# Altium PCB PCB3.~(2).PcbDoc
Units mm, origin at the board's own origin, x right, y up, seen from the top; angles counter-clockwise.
Board outline 50 x 50 mm, 4 copper layers (Top Layer, Internal Plane 1, Internal Plane 2, Bottom Layer), stack 0.462 mm thick; 11 components, 11 nets, 36 pads, 0 vias.
Unrouted connection lines stored in the file: 21.
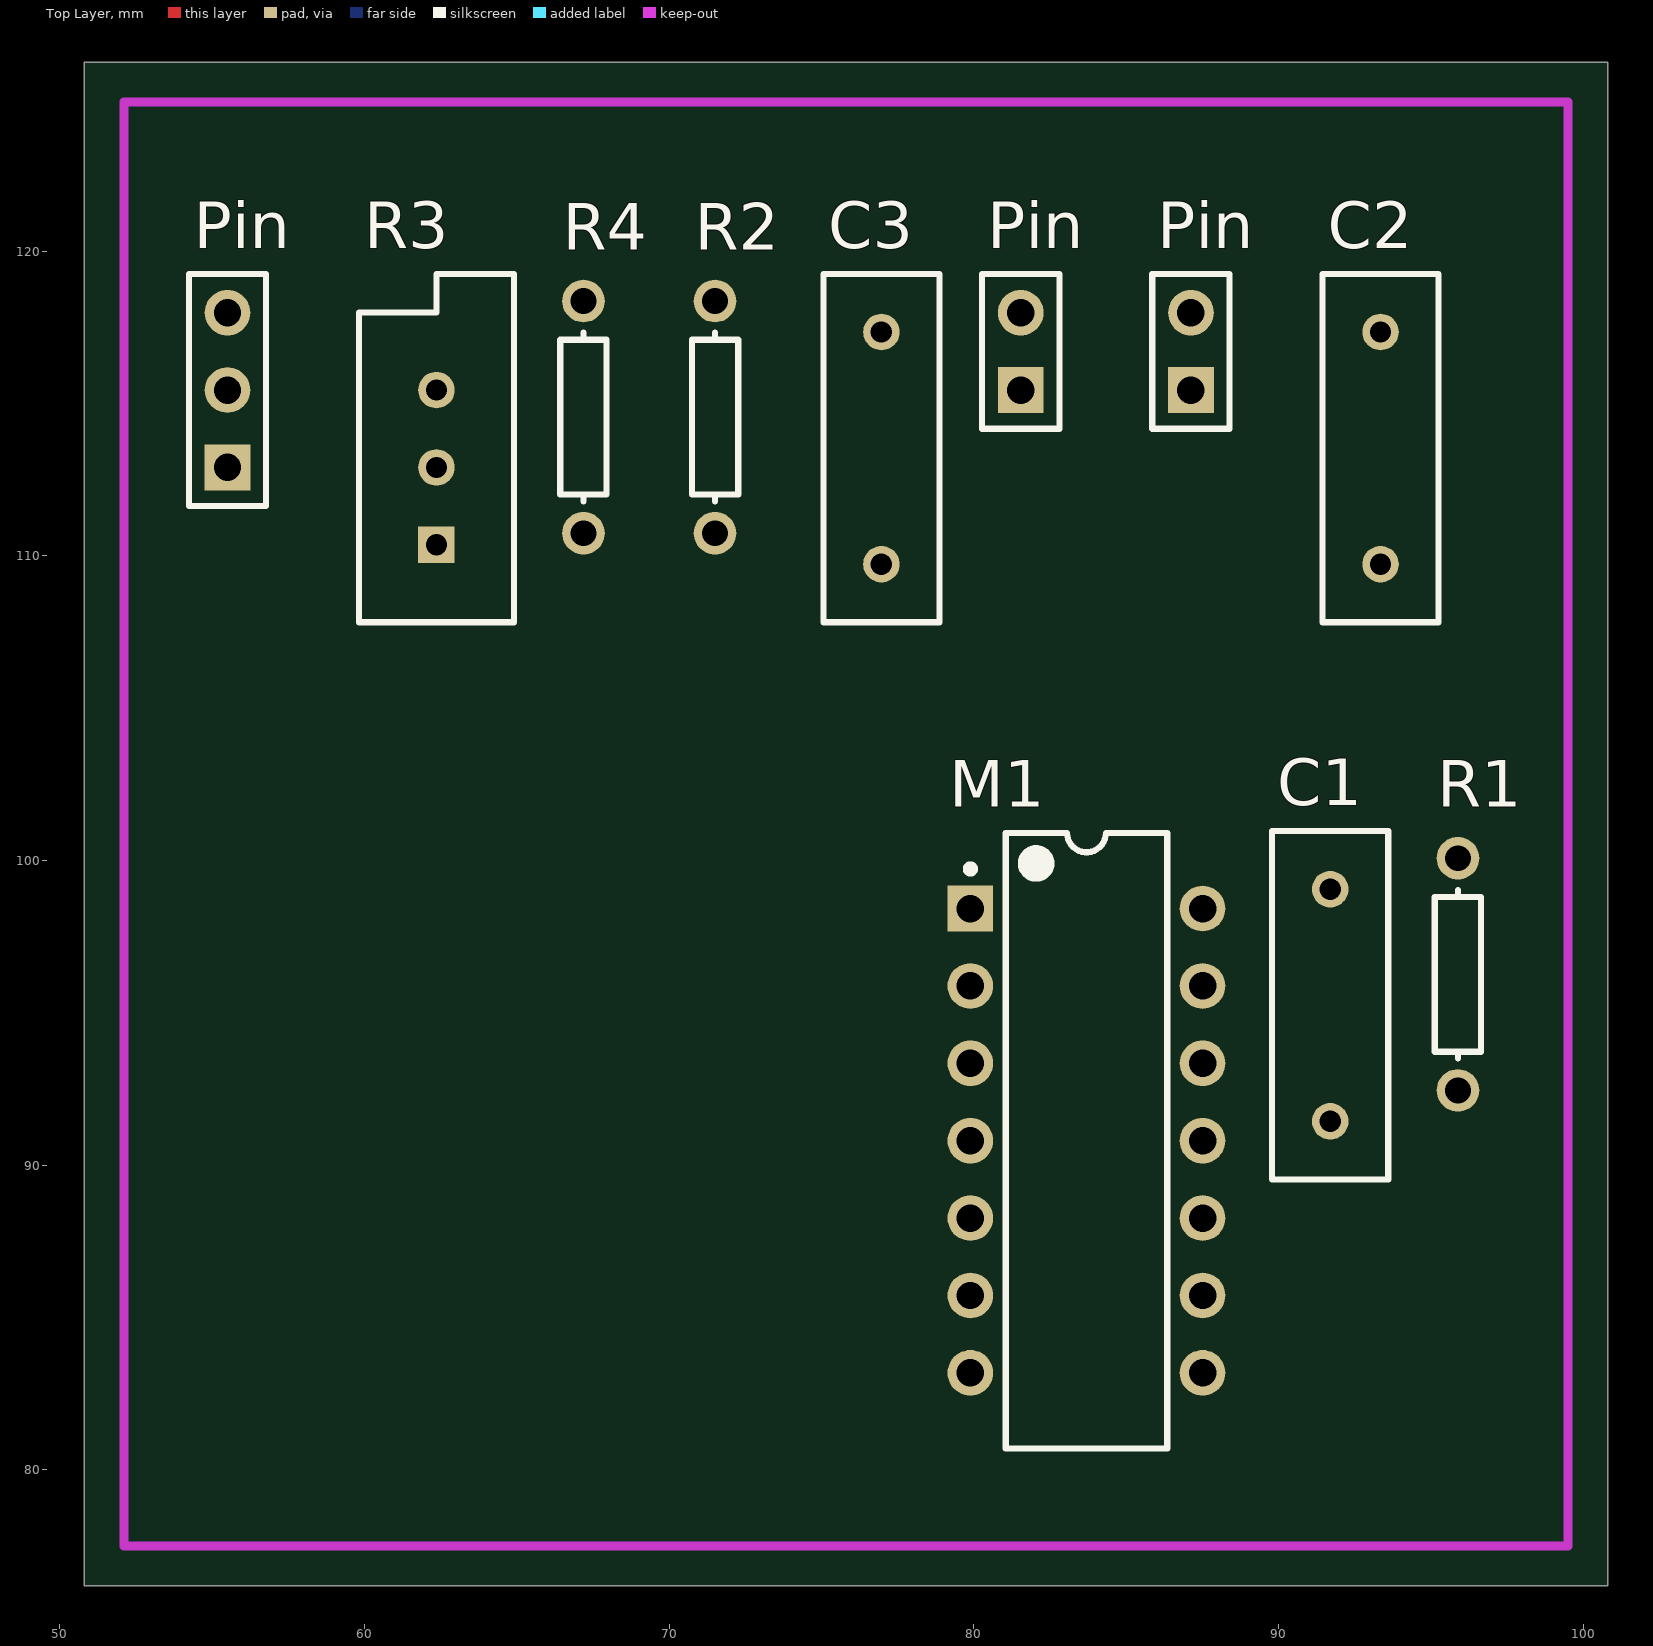
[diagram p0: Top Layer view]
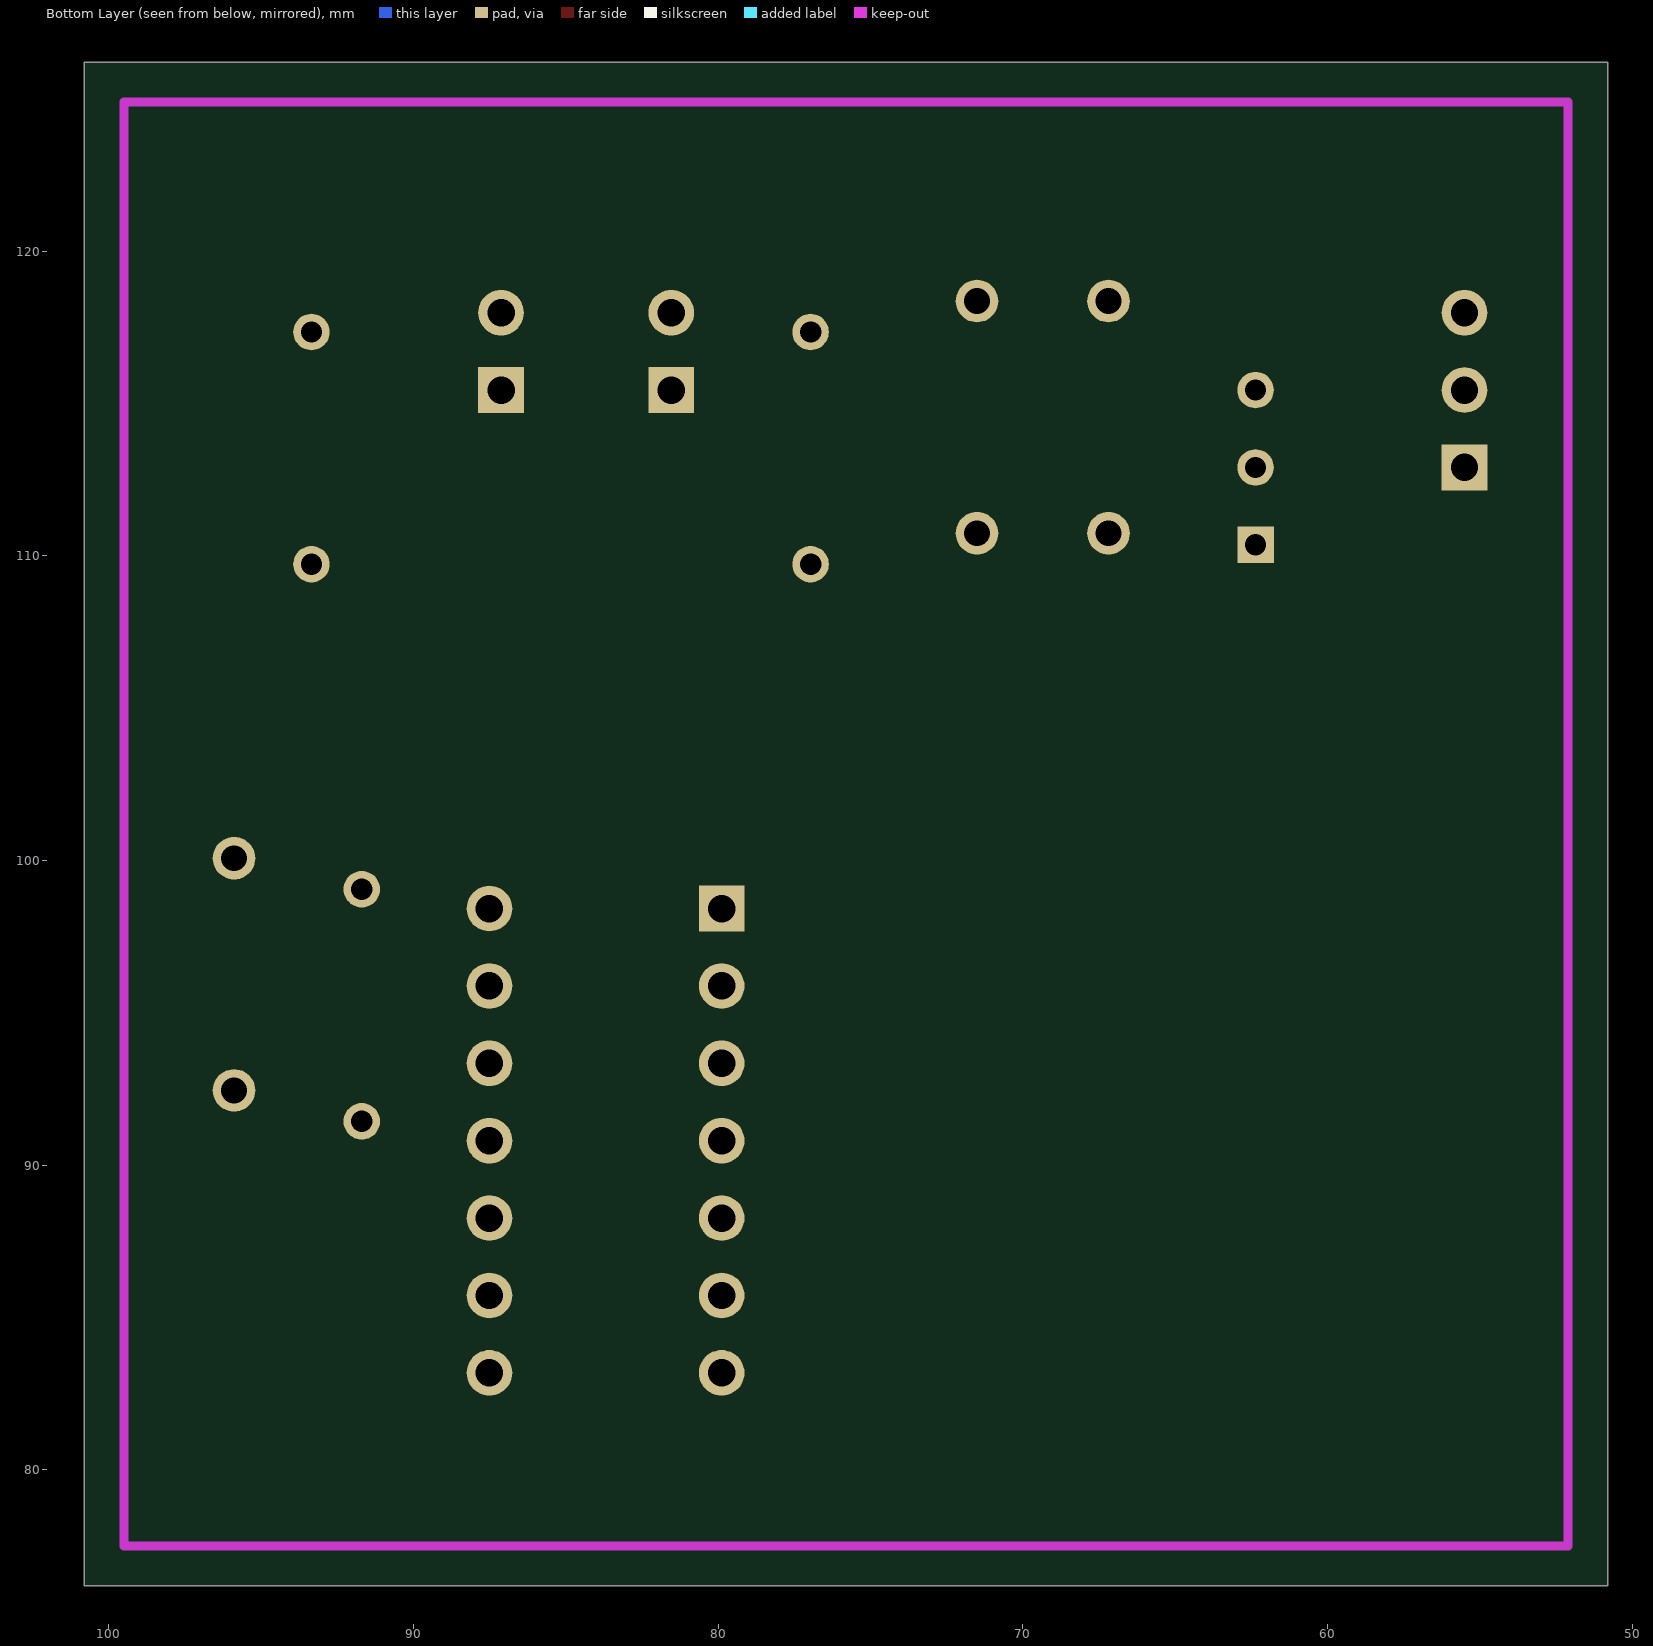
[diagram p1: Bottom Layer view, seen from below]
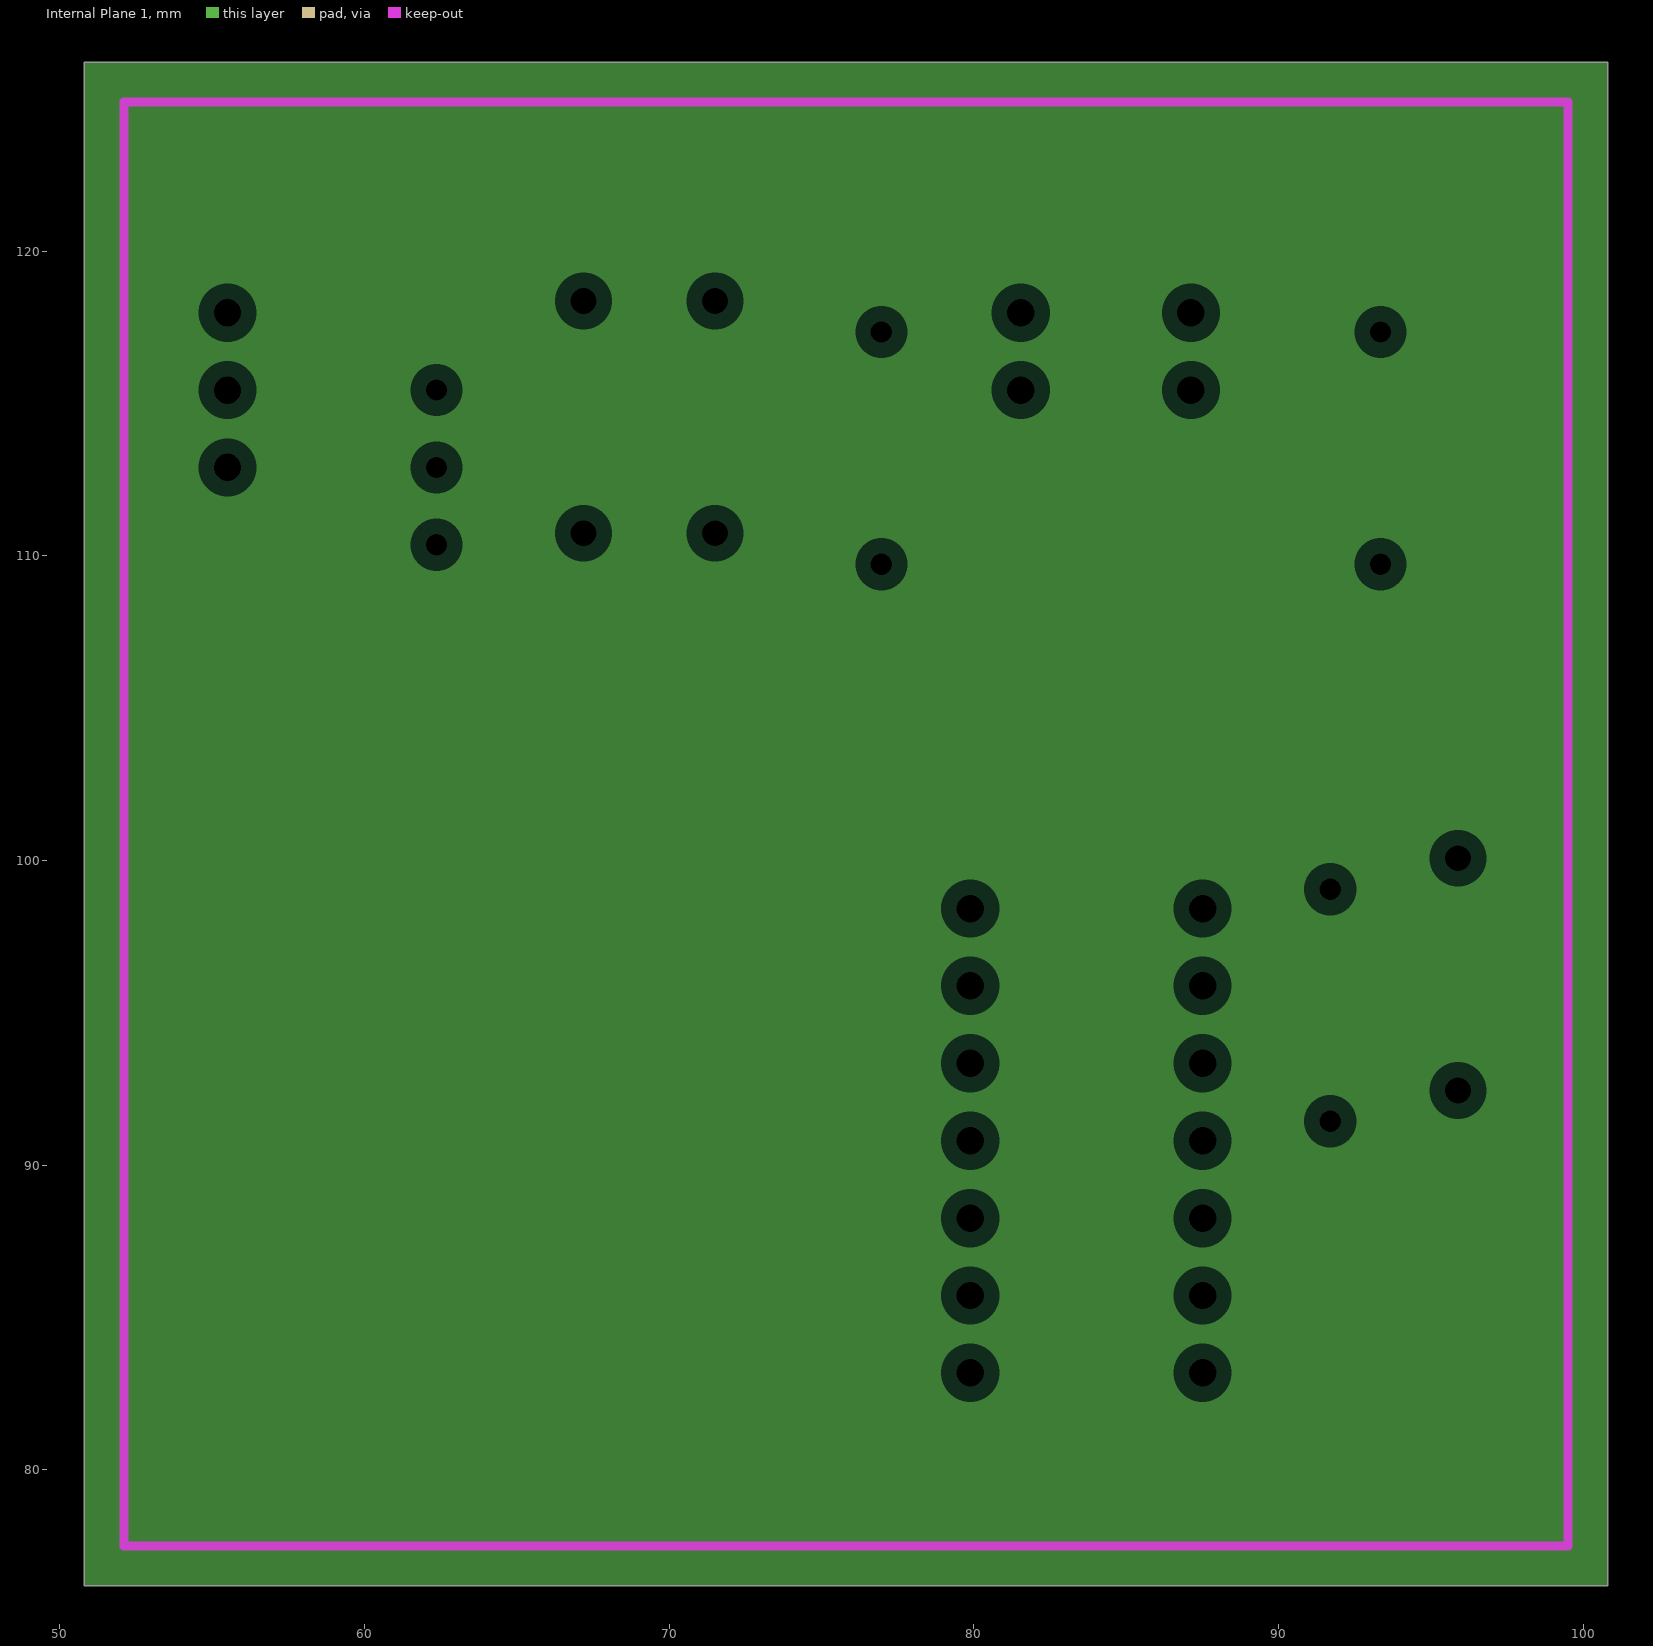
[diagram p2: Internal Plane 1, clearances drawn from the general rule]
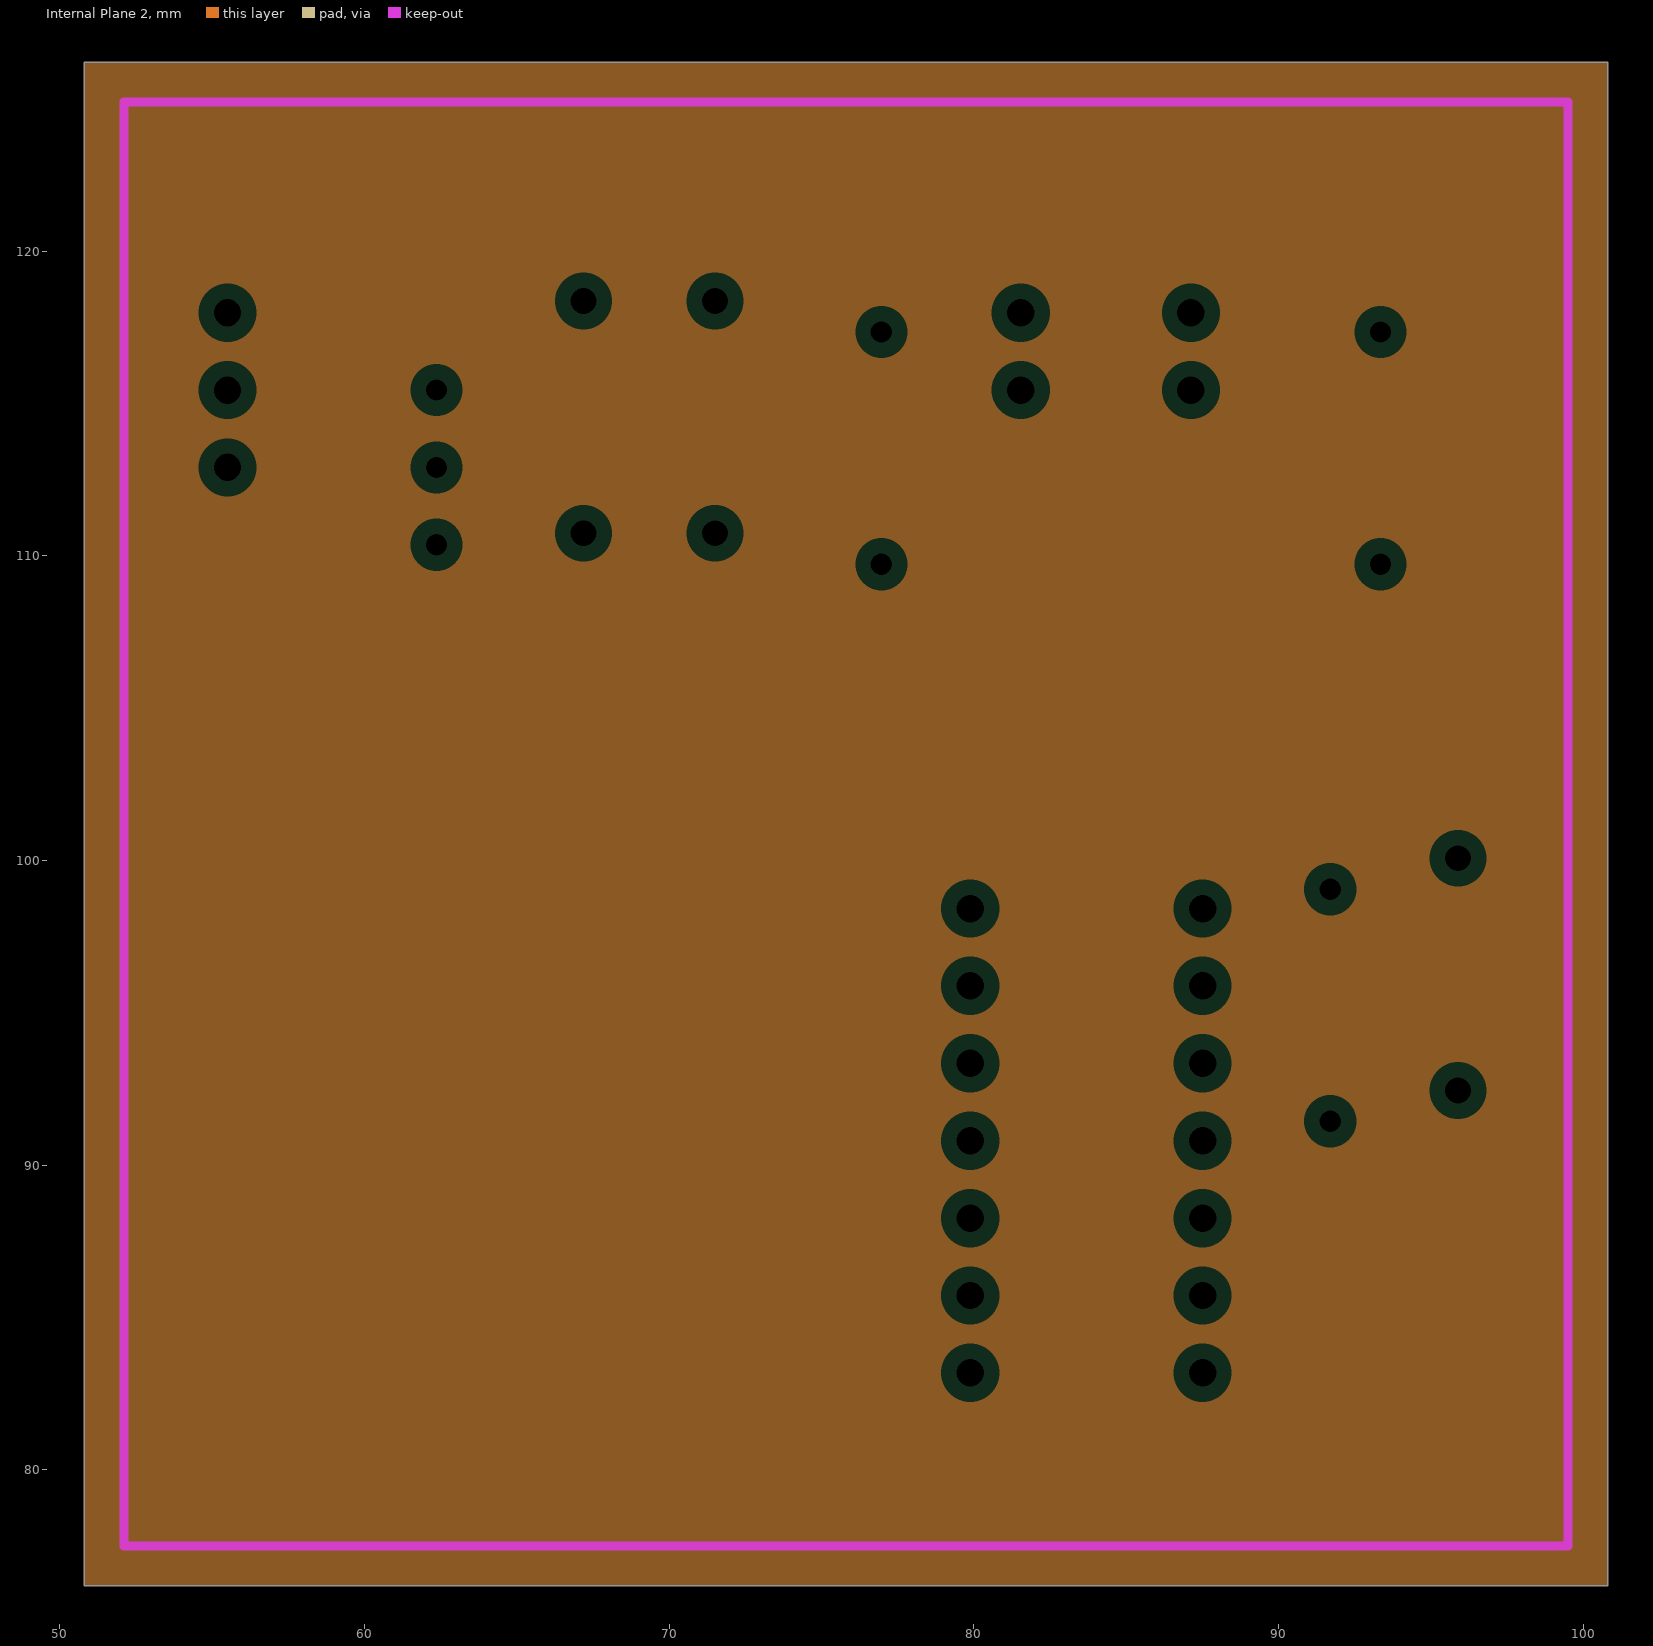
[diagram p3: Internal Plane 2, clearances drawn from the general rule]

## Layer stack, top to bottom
Top Solder: solder mask 0.0102, Solder Resist, Dk 3.5
Top Layer: signal copper 0.0356
Internal Plane 1: plane copper 0.0356
Internal Plane 2: plane copper 0.0356
Dielectric 1: dielectric 0.32, FR-4, Dk 4.8
Bottom Layer: signal copper 0.0356
Bottom Solder: solder mask 0.0102, Solder Resist, Dk 3.5

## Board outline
50.8,76.2 100.8,76.2 100.8,126.2 50.8,126.2

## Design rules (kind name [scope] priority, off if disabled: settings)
Clearance [All] p1: gap=0.8
PlaneClearance [All] p1: clearance=0.508
PlaneConnect [All] p1: planeconnectstyle=Relief reliefexpansion=0.508 reliefentries=4 reliefconductorwidth=0.254 reliefairgap=0.254
PolygonConnect [All] p1: connectstyle=Relief reliefconductorwidth=0.254 reliefentries=4 polygonreliefangle="90 Angle" airgapwidth=0.254
RoutingVias [All] p1: holewidth=0.8 width=1.6 viastyle="Through Hole" minholewidth=0.711 minwidth=1.27 maxholewidth=0.711 maxwidth=1.27
SolderMaskExpansion [All] p1: expansion=0.102
Width [All] p1: maxlimit=0.5 minlimit=0.5 preferedwidth=0.5
28 further rules are at their usual default settings.

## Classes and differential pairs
component class LEPROJETDENTHANETWILLIAMZANG: C1 C2 C3 M1 Pin R1 R2 R3 R4

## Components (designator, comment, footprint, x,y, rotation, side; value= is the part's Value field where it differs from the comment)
C1 "Cap" RAD-0.3 91.694,95.25 r90 top
C2 "Cap" RAD-0.3 93.345,113.538 r90 top
C3 "Cap" RAD-0.3 76.962,113.538 r90 top
M1 "ALD1106" DIP-14 83.693,90.805 r0 top
Pin "IN" HDR1X2 81.534,115.443 r90 top
Pin "OUT" HDR1X2 87.122,115.443 r90 top
Pin "Header 3" HDR1X3 55.499,112.903 r90 top
R1 "Res1" AXIAL-0.3 95.885,96.266 r90 top
R2 "Res1" AXIAL-0.3 71.501,114.554 r90 top
R3 "RPot" VR5 62.357,112.903 r90 top
R4 "Res1" AXIAL-0.3 67.183,114.554 r90 top

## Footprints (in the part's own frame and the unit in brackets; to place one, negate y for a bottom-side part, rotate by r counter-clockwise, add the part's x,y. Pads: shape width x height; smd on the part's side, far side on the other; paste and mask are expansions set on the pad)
AXIAL-0.3 [mm] "Axial Device, Thru-Hole; 2 Leads; 0.3 in Pin Spacing"
  round 1.4 hole 0.85: 1(-3.81,0) 2(3.81,0)
  silkscreen extent -2.77,-0.76 2.77,0.76
DIP-14 [mm] "DIP, 14-Pin, Row Spacing 7.62 mm, Pitch 2.54 mm"
  rect 1.5x1.5 hole 0.9: 1(-3.81,7.62)
  round 1.5 hole 0.9: 2(-3.81,5.08) 3(-3.81,2.54) 4(-3.81,0) 5(-3.81,-2.54) 6(-3.81,-5.08) 7(-3.81,-7.62) 8(3.81,-7.62) 9(3.81,-5.08) 10(3.81,-2.54) 11(3.81,0) 12(3.81,2.54) 13(3.81,5.08) 14(3.81,7.62)
  silkscreen extent -3.93,-10.1 2.65,10.1, body extent -3.6,-10.1 3.6,10.1, height 5.08
HDR1X2 [mm] "Connector; Header; 2 Position"
  rect 1.5x1.5 hole 0.9: 1(0,0)
  round 1.5 hole 0.9: 2(2.54,0)
  silkscreen extent -1.27,-1.27 3.81,1.27
HDR1X3 [mm] "Connector; Header; 3 Position"
  rect 1.5x1.5 hole 0.9: 1(0,0)
  round 1.5 hole 0.9: 2(2.54,0) 3(5.08,0)
  silkscreen extent -1.27,-1.27 6.35,1.27
RAD-0.3 [mm] "Radial Cap, Thru-Hole; 2 Leads; 0.3 in Pin Spacing"
  round 1.2 hole 0.7: 1(-3.81,0) 2(3.81,0)
  silkscreen extent -5.71,-1.91 5.71,1.91
VR5 [mm] "Thru-Hole; 3 Leads"
  rect 1.2x1.2 hole 0.7: 1(-2.54,0)
  round 1.2 hole 0.7: 2(0,0) 3(2.54,0)
  silkscreen extent -5.08,-2.54 6.35,2.54

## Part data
C1 C2 C3: "Capacitor"
M1: "Quad N-channel matched MOSFET array"
Pin Pin: library part "Header 2", "Header, 2-Pin"
Pin: "Header, 3-Pin"
R1 R2 R4: "Resistor"
R3: "Potentiometer"

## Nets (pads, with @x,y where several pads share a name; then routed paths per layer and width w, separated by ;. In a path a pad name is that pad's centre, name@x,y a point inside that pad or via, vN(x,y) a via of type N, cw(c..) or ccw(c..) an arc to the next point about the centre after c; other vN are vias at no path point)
GND: C3.2 Pin.1@81.534,115.443 Pin.1@87.122,115.443 Pin.3 R2.1
NetC1_1: C1.1 M1.1 R1.1
NetC1_2: C1.2 Pin.2@87.122,117.983
NetC2_1: C2.1 Pin.2@81.534,117.983
NetC2_2: C2.2 M1.2 R2.2
NetC3_1: C3.1 M1.3 M1.14
NetM1_4: M1.4 M1.7
NetM1_5: M1.5 M1.6
NetM1_9: M1.9 M1.10 M1.13 R4.1
NetPin_1: Pin.1@55.499,112.903 R1.2 R3.2 R3.3
NetR3_1: R3.1 R4.2
pads on no net: M1.8 M1.11 M1.12 Pin.2@55.499,115.443

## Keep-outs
Keep-Out Layer:
  lines w0.3: 52.1,77.5 52.1,124.9 99.5,124.9 99.5,77.5 52.1,77.5

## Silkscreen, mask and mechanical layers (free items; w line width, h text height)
Drill Drawing:
  text ".LEGEND" at 57.874,102.235 h1.52
  text "Drill Drawing." at 57.874,99.695 h1.52

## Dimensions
52.1,77.5 to 52.1,124.9 on Mechanical 1
52.1,77.5 to 99.5,77.5 on Mechanical 1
